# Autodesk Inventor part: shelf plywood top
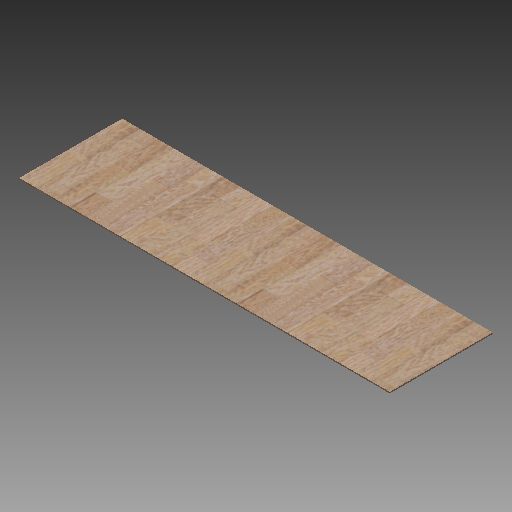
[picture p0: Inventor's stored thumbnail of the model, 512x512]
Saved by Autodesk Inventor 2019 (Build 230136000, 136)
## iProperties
Created: 2013-07
Part Number: shelf plywood top
Material: Generic
Document SubType Name: Modeling
Designer: Patrick Rice
Density: 1 g/cm^3
Appearance: Red Oak - Natural
Author: Patrick Rice
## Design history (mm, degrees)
sketch "Sketch1"
  geometry: L1 (914.4, -254)-(-914.4, -254); L2 (-914.4, -254)-(-914.4, 254); L3 (-914.4, 254)-(914.4, 254); L4 (914.4, 254)-(914.4, -254); L5 (914.4, -254)-(-914.4, 254); L6 (-914.4, -254)-(914.4, 254); 9 further points
  constraints: 12 end point, 8 point on line, 2 midpoint, 2 parallel, 1 horizontal, 1 perpendicular
  dimensions: "d0" = 1828.8 distance of L2.end L3.end; "d1" = 508 distance of L1.end L2.end
extrude "Extrusion2" new body sketch "Sketch1" distance "d12" = 6.35; taper "d13" = 0 deg
body "Solid2"
